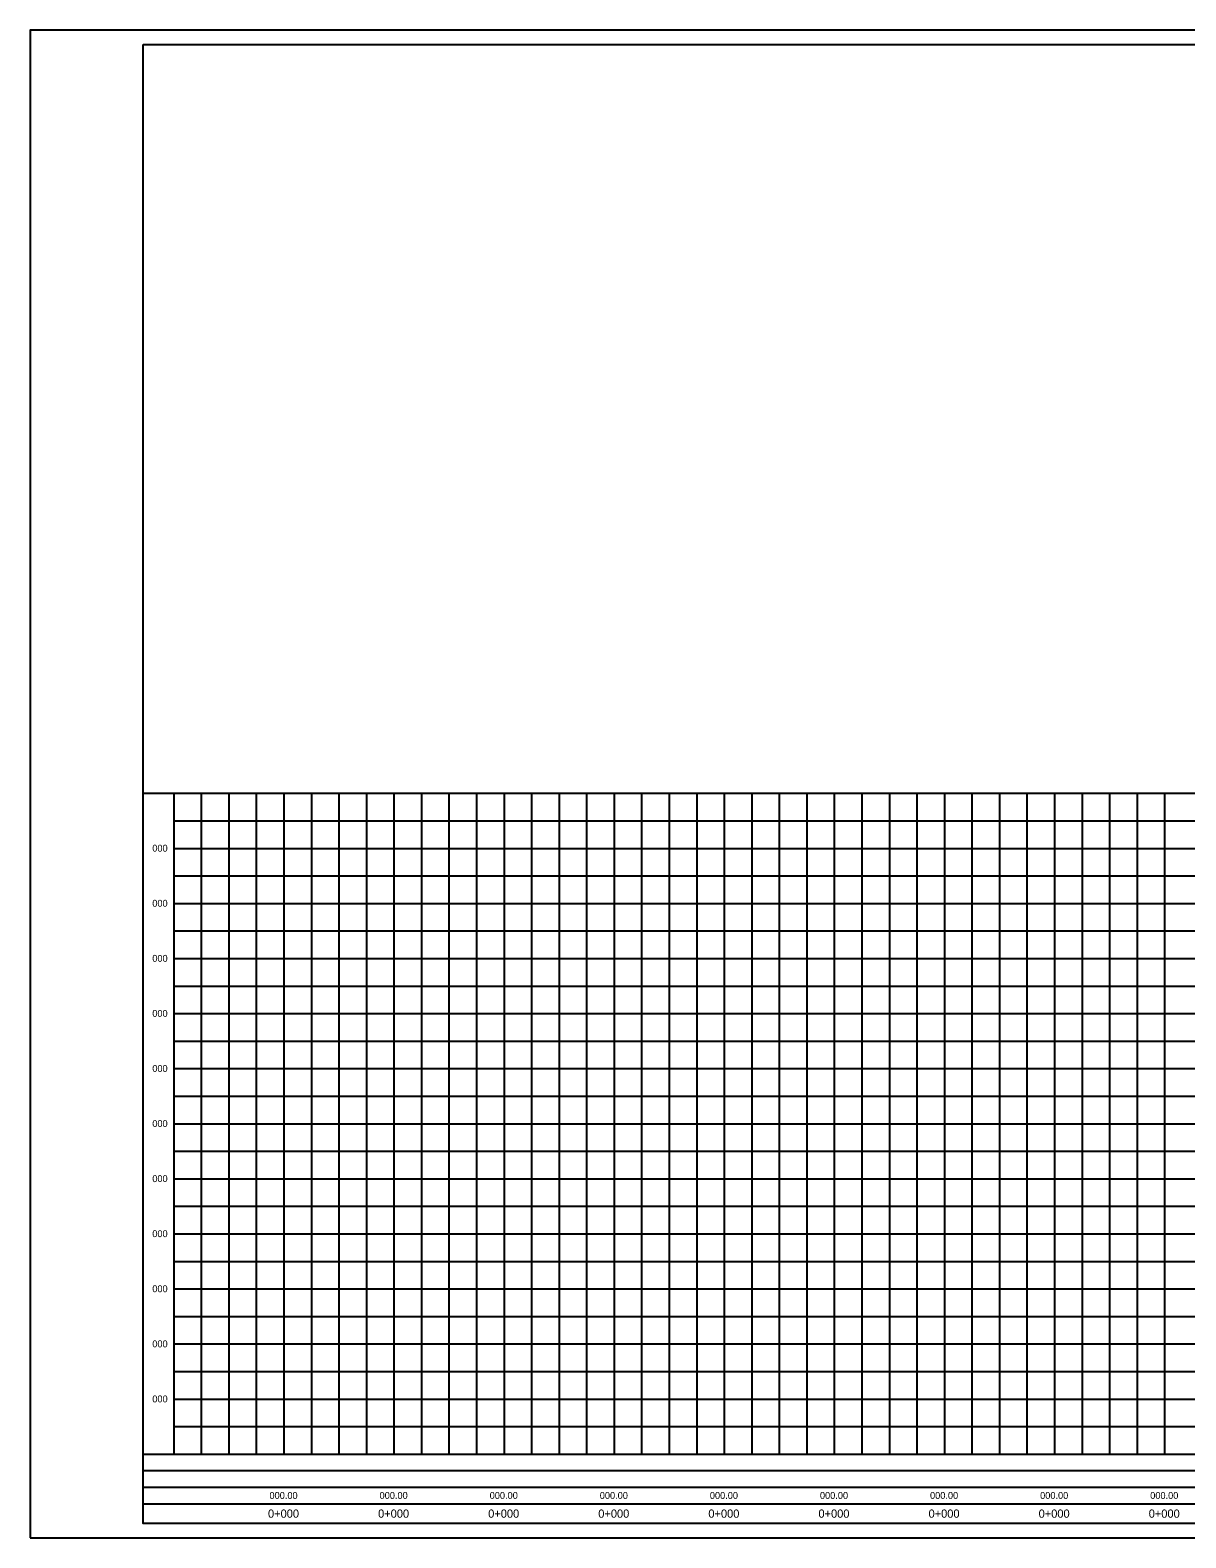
# Model space of a CAD drawing. Extents: x 613360 to 613780, y 4825621 to 4825911.
# Drawn here: x 613359.6 to 613569.5, y 4825620.9 to 4825894.7 of the extents above; entities that cross this region are included whole.
import ezdxf

# ---------------------------------------------------------------- set-up
doc = ezdxf.new("R2010")
doc.units = 0
for name, color, linetype in [('G-ANNO-TEXT', 7, 'Continuous'), ('G-GRID-MAJ', 7, 'Continuous'), ('G-GRID-MIN', 7, 'Continuous'), ('G-TTLB-OTLN', 7, 'Continuous'), ('G-TTLB-OTLN-PB', 7, 'Continuous')]:
    doc.layers.add(name, color=color, linetype=linetype)

msp = doc.modelspace()

# ---------------------------------------------------------------- linework, layer by layer
at = {"layer": 'G-GRID-MAJ'}
for p, q in [((613385.73, 4825636.11), (613385.73, 4825756.11)), ((613405.73, 4825636.11), (613405.73, 4825756.11)), ((613425.73, 4825636.11), (613425.73, 4825756.11)), ((613445.73, 4825636.11), (613445.73, 4825756.11)), ((613465.73, 4825636.11), (613465.73, 4825756.11)), ((613485.73, 4825636.11), (613485.73, 4825756.11)), ((613505.73, 4825636.11), (613505.73, 4825756.11)), ((613525.73, 4825636.11), (613525.73, 4825756.11)), ((613545.73, 4825636.11), (613545.73, 4825756.11)), ((613565.73, 4825636.11), (613565.73, 4825756.11)), ((613385.73, 4825746.11), (613705.73, 4825746.11)), ((613385.73, 4825736.11), (613705.73, 4825736.11)), ((613385.73, 4825726.11), (613705.73, 4825726.11)), ((613385.73, 4825716.11), (613705.73, 4825716.11)), ((613385.73, 4825706.11), (613705.73, 4825706.11)), ((613385.73, 4825696.11), (613705.73, 4825696.11)), ((613385.73, 4825686.11), (613705.73, 4825686.11)), ((613385.73, 4825676.11), (613705.73, 4825676.11)), ((613385.73, 4825666.11), (613705.73, 4825666.11)), ((613385.73, 4825656.11), (613705.73, 4825656.11)), ((613385.73, 4825646.11), (613705.73, 4825646.11))]:
    msp.add_line(p, q, dxfattribs=at)
at = {"layer": 'G-GRID-MIN'}
for p, q in [((613390.73, 4825636.11), (613390.73, 4825756.11)), ((613395.73, 4825636.11), (613395.73, 4825756.11)), ((613400.73, 4825636.11), (613400.73, 4825756.11)), ((613410.73, 4825636.11), (613410.73, 4825756.11)), ((613415.73, 4825636.11), (613415.73, 4825756.11)), ((613420.73, 4825636.11), (613420.73, 4825756.11)), ((613430.73, 4825636.11), (613430.73, 4825756.11)), ((613435.73, 4825636.11), (613435.73, 4825756.11)), ((613440.73, 4825636.11), (613440.73, 4825756.11)), ((613450.73, 4825636.11), (613450.73, 4825756.11)), ((613455.73, 4825636.11), (613455.73, 4825756.11)), ((613460.73, 4825636.11), (613460.73, 4825756.11)), ((613470.73, 4825636.11), (613470.73, 4825756.11)), ((613475.73, 4825636.11), (613475.73, 4825756.11)), ((613480.73, 4825636.11), (613480.73, 4825756.11)), ((613490.73, 4825636.11), (613490.73, 4825756.11)), ((613495.73, 4825636.11), (613495.73, 4825756.11)), ((613500.73, 4825636.11), (613500.73, 4825756.11)), ((613510.73, 4825636.11), (613510.73, 4825756.11)), ((613515.73, 4825636.11), (613515.73, 4825756.11)), ((613520.73, 4825636.11), (613520.73, 4825756.11)), ((613530.73, 4825636.11), (613530.73, 4825756.11)), ((613535.73, 4825636.11), (613535.73, 4825756.11)), ((613540.73, 4825636.11), (613540.73, 4825756.11)), ((613550.73, 4825636.11), (613550.73, 4825756.11)), ((613555.73, 4825636.11), (613555.73, 4825756.11)), ((613560.73, 4825636.11), (613560.73, 4825756.11)), ((613385.73, 4825751.11), (613705.73, 4825751.11)), ((613385.73, 4825741.11), (613705.73, 4825741.11)), ((613385.73, 4825731.11), (613705.73, 4825731.11)), ((613385.73, 4825721.11), (613705.73, 4825721.11)), ((613385.73, 4825711.11), (613705.73, 4825711.11)), ((613385.73, 4825701.11), (613705.73, 4825701.11)), ((613385.73, 4825691.11), (613705.73, 4825691.11)), ((613385.73, 4825681.11), (613705.73, 4825681.11)), ((613385.73, 4825671.11), (613705.73, 4825671.11)), ((613385.73, 4825661.11), (613705.73, 4825661.11)), ((613385.73, 4825651.11), (613705.73, 4825651.11)), ((613385.73, 4825641.11), (613705.73, 4825641.11))]:
    msp.add_line(p, q, dxfattribs=at)
at = {"layer": 'G-TTLB-OTLN'}
for p, q in [((613380.09, 4825756.11), (613774.18, 4825756.11)), ((613380.09, 4825636.11), (613710.78, 4825636.11)), ((613380.09, 4825633.11), (613774.18, 4825633.11)), ((613380.09, 4825630.11), (613749.42, 4825630.11)), ((613380.09, 4825627.11), (613749.42, 4825627.11))]:
    msp.add_line(p, q, dxfattribs=at)
msp.add_lwpolyline([(613380.09, 4825892.08), (613774.18, 4825892.08), (613774.18, 4825623.51), (613380.09, 4825623.51)], close=True, dxfattribs=at)
at = {"layer": 'G-TTLB-OTLN-PB'}
for p, q in [((613364.58, 4825894.68), (613359.58, 4825894.68)), ((613359.58, 4825894.68), (613359.58, 4825888.68)), ((613359.58, 4825626.91), (613359.58, 4825620.91)), ((613359.58, 4825620.91), (613364.58, 4825620.91))]:
    msp.add_line(p, q, dxfattribs=at)
msp.add_lwpolyline([(613359.58, 4825620.91), (613780.27, 4825620.91), (613780.27, 4825894.68), (613359.58, 4825894.68)], close=True, dxfattribs=at)

# ---------------------------------------------------------------- texts
at = {"layer": 'G-ANNO-TEXT'}
for p in [(613381.77, 4825745.51), (613381.77, 4825735.51), (613381.77, 4825725.51), (613381.77, 4825715.51), (613381.77, 4825695.51), (613381.77, 4825685.51), (613381.77, 4825675.51), (613381.77, 4825665.51), (613381.77, 4825655.51), (613381.77, 4825645.51)]:
    msp.add_text('000', height=1.25, rotation=360, dxfattribs=at).set_placement(p)
for s, height, p in [('000', 1.25, (613381.77, 4825705.51)), ('000.00', 1.25, (613403.06, 4825627.98)), ('000.00', 1.25, (613423.06, 4825627.98)), ('000.00', 1.25, (613443.06, 4825627.98)), ('000.00', 1.25, (613463.06, 4825627.98)), ('000.00', 1.25, (613483.06, 4825627.98)), ('000.00', 1.25, (613503.06, 4825627.98)), ('000.00', 1.25, (613523.06, 4825627.98)), ('000.00', 1.25, (613543.06, 4825627.98)), ('000.00', 1.25, (613563.06, 4825627.98)), ('0+000', 1.5, (613402.79, 4825624.56)), ('0+000', 1.5, (613422.79, 4825624.56)), ('0+000', 1.5, (613442.79, 4825624.56)), ('0+000', 1.5, (613462.79, 4825624.56)), ('0+000', 1.5, (613482.79, 4825624.56)), ('0+000', 1.5, (613502.79, 4825624.56)), ('0+000', 1.5, (613522.79, 4825624.56)), ('0+000', 1.5, (613542.79, 4825624.56)), ('0+000', 1.5, (613562.79, 4825624.56))]:
    msp.add_text(s, height=height, dxfattribs=at).set_placement(p)

doc.saveas('drawing.dxf')
